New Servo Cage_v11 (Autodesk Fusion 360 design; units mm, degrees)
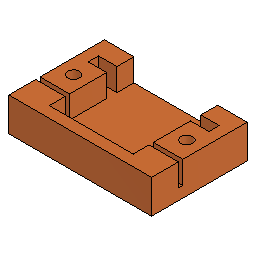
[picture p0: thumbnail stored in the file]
sketch "Sketch1" plane through (0, 0, 0) normal (0, 0, 1) x axis (1, 0, 0)
  line L1 (-14.4, -13) -> (14.4, -13)
  line L2 (-14.4, 13) -> (-14.4, -13)
  line L3 (14.4, 13) -> (-14.4, 13)
  line L4 (14.4, -13) -> (14.4, 13)
  line L5 (-14.4, 13) -> (14.4, -13)
  line L6 (14.4, 13) -> (-14.4, -13)
  line L7 (20.788, 7) -> (-24.9538, 7)
  line L8 (0, 13) -> (0, 0)
  line L9 (-19.4, 5.6) -> (19.4, 5.6)
  line L10 (-19.4, 8.4) -> (-19.4, 5.6)
  line L11 (19.4, 8.4) -> (-19.4, 8.4)
  line L12 (19.4, 5.6) -> (19.4, 8.4)
  line L13 (-19.4, 8.4) -> (19.4, 5.6)
  line L14 (19.4, 8.4) -> (-19.4, 5.6)
  line L15 (19.4, 5.6) -> (-19.4, 5.6)
  line L16 (19.4, 0.6) -> (19.4, 5.6)
  line L17 (-19.4, 0.6) -> (19.4, 0.6)
  line L18 (-19.4, 5.6) -> (-19.4, 0.6)
  line L19 (-19.4, 0) -> (0, 0)
  line L20 (19.4, 8.4) -> (-19.4, 8.4)
  line L21 (19.4, 11.4) -> (19.4, 8.4)
  line L22 (-19.4, 11.4) -> (19.4, 11.4)
  line L23 (-19.4, 8.4) -> (-19.4, 11.4)
  line L24 (-16.4, 0.6) -> (-16.4, 11.4)
  line L25 (16.4, 0.6) -> (16.4, 11.4)
  line L26 (11.4, 13) -> (-11.4, 13)
  line L27 (11.4, -10) -> (11.4, 13)
  line L28 (-11.4, -10) -> (11.4, -10)
  line L29 (-11.4, 13) -> (-11.4, -10)
  line L30 (-19.4, -13) -> (19.4, -13)
  line L31 (-19.4, 13) -> (-19.4, -13)
  line L32 (19.4, 13) -> (-19.4, 13)
  line L33 (19.4, -13) -> (19.4, 13)
  line L34 (-19.4, 13) -> (19.4, -13)
  line L35 (19.4, 13) -> (-19.4, -13)
  line L36 (19.4, -5.1) -> (-19.4, -5.1)
  line L37 (-19.4, -5.7) -> (19.4, -5.7)
  line L38 (-19.4, -4.5) -> (-19.4, -5.7)
  line L39 (19.4, -4.5) -> (-19.4, -4.5)
  line L40 (19.4, -5.7) -> (19.4, -4.5)
  line L41 (-19.4, -4.5) -> (19.4, -5.7)
  line L42 (19.4, -4.5) -> (-19.4, -5.7)
  line L43 (16.4, -13) -> (16.4, 0.6)
  line L44 (-16.4, -13) -> (-16.4, 0.6)
  circle C1 centre (-15.4, 0.6) radius 1.6
  circle C2 centre (15.4, 0.6) radius 1.6
  point P6 (0, 0)
  point P1 (0, 0)
  point P9 (0, 0)
  point P10 (0, 13)
  point P15 (0, 7)
  point P19 (-19.4, 0)
  point P23 (-16.4, 11.4)
  point P24 (-16.4, 0.6)
  point P25 (16.4, 11.4)
  point P26 (16.4, 0.6)
  point P27 (-11.4, 13)
  point P35 (0, 0)
  point P36 (-19.4, -5.1)
  point P37 (19.4, -5.1)
  point P42 (0, -5.1)
  point P43 (16.4, -13)
  point P44 (-16.4, -13)
  point P45 (-15.4, 0.6)
  point P3 (-14.4, -13)
  point P4 (-14.4, 13)
  point P2 (14.4, -13)
  point P13 (-19.4, 8.4)
  point P14 (19.4, 8.4)
  point P12 (-19.4, 5.6)
  point P18 (-19.4, 0.6)
  point P17 (19.4, 0.6)
  point P22 (-19.4, 11.4)
  point P21 (19.4, 11.4)
  point P28 (11.4, 13)
  point P30 (-11.4, -10)
  point P33 (-19.4, 13)
  point P34 (19.4, 13)
  point P32 (-19.4, -13)
  point P40 (-19.4, -4.5)
  point P41 (19.4, -4.5)
  point P39 (-19.4, -5.7)
  horizontal L1
  perpendicular L1 L2
  parallel L1 L3
  parallel L2 L4
  coincident L5 P6
  coincident L6 P6
  coincident P1 P6
  perpendicular L4 L7
  coincident P6 P9
  midpoint L3 P10
  horizontal L9
  perpendicular L9 L10
  parallel L9 L11
  parallel L10 L12
  coincident L13 P15
  coincident L14 P15
  coincident L7 P15
  coincident L8 P15
  horizontal L15
  vertical L16
  horizontal L17
  vertical L18
  coincident L18 P19
  perpendicular L18 L19
  horizontal L20
  vertical L21
  horizontal L22
  vertical L23
  coincident L22 P23
  coincident L17 P24
  perpendicular L17 L24
  symmetric L8 P23 P25
  symmetric L8 P24 P26
  horizontal L26
  vertical L27
  horizontal L28
  vertical L29
  coincident L3 P27
  horizontal L30
  perpendicular L30 L31
  parallel L30 L32
  parallel L31 L33
  coincident L34 P35
  coincident L35 P35
  coincident P9 P35
  coincident L31 P36
  coincident L33 P37
  perpendicular L33 L36
  horizontal L37
  perpendicular L37 L38
  parallel L37 L39
  parallel L38 L40
  coincident L41 P42
  coincident L42 P42
  midpoint L36 P42
  coincident L30 P43
  perpendicular L30 L43
  coincident L30 P44
  perpendicular L30 L44
  coincident L17 P45
  symmetric L8 C1 C2
  dimension "d1" distance P3 P4 = 26 (= "23 mm + 3 mm")
  dimension "d2" distance P2 P3 = 28.8 (= "22.8 mm + 6 mm")
  dimension "d3" distance L1 L7 = 20 (= "15.6 mm + d5 / 2 + 3 mm")
  dimension "d4" distance P13 P14 = 38.8 (= "d2 + 10 mm")
  dimension "d5" distance P12 P13 = 2.8
  dimension "d6" distance P12 P18 = 5
  dimension "d7" distance P17 P18 = 38.8 (= "d4")
  dimension "d13" distance P13 P22 = 3
  dimension "d14" distance P21 P22 = 38.8 (= "d4")
  dimension "d15" distance L18 L24 = 3
  dimension "d16" distance P27 P28 = 22.8
  dimension "d17" distance P27 P30 = 23
  dimension "d18" distance L2 L29 = 3
  dimension "d25" distance P33 P34 = 38.8 (= "d4")
  dimension "d26" distance P32 P33 = 26 (= "d1")
  dimension "d29" distance L28 L36 = 4.9 (= "4.4 mm + ( 1 / 2 ) * 1 mm")
  dimension "d30" distance P40 P41 = 38.8 (= "d4")
  dimension "d31" distance P39 P40 = 1.2
  dimension "d33" diameter C1 = 3.2
  dimension "d34" distance L31 P45 = 4
extrude "Extrude1" new body sketch "Sketch1" profile of L1 L2 L3 L4 L9 L10 L11 L12 L15 L16 L17 L18 L20 L21 L22 L23 L24 L25 L27 L28 L29 L30 L31 L32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 along normal blind 9.15 (= "( ( 12.3 / 2 ) * 1 mm ) + 3 mm")
extrude "Extrude2" add sketch "Sketch1" profile of L2 L3 L4 L9 L11 L15 L17 L20 L22 L24 L25 L26 L27 L28 L29 L31 L32 L33 L37 L38 L39 L40 L43 L44 along normal blind 3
